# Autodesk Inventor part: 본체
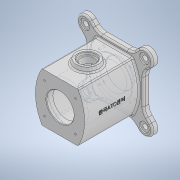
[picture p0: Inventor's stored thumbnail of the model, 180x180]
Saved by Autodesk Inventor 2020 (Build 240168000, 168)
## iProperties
Created: 2022-01
Part Number: 본체
Material: 일반
Document SubType Name: Modeling
Designer: user
Density: 1 g/cm^3
Appearance: 기본값
Mass: 458.422 g
Surface Area: 905.599 cm^2
Volume: 458.422 cm^3
Author: user
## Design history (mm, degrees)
sketch "스케치1"
  geometry: L1 (-32.942, -45)-(32.942, -45); L2 (32.942, 45)-(-32.942, 45); L3 (-45, -45)-(45, 45); L4 (45, -45)-(-45, 45); L5 (0, 0)-(0, -45); A1 r 90 centre (45, 0) between (-32.942, 45) and (-32.942, -45); A2 r 90 centre (-45, 0) between (32.942, -45) and (32.942, 45)
  constraints: 10 end point, 4 point on circle, 3 symmetric about line, 2 centre point, 2 midpoint, 1 horizontal, 1 parallel, 1 other
  dimensions: "d2" = 180 diameter of A1; "d3" = 90 distance between parallel lines of L1 L2; "d4" = 90 distance of A1.centre A2.centre
extrude "돌출1" new body sketch "스케치1" distance "d5" = 110; taper "d6" = 0 deg
sketch "스케치2"
  geometry: L1 (53, -53)-(-53, -53); L2 (-53, -53)-(-53, 53); L3 (-53, 53)-(53, 53); L4 (53, 53)-(53, -53); L5 (53, -53)-(-53, 53); L6 (-53, -53)-(53, 53); L7 (0, 0)-(0, 74); L8 (54.447, -54.447)-(-54.447, 54.447); L9 (65.054, -43.841)-(-43.841, 65.054); L10 (-65.054, 43.841)-(43.841, -65.054); L11 (-54.447, -54.447)-(54.447, 54.447); L12 (-43.841, -65.054)-(65.054, 43.841); L13 (43.841, 65.054)-(-65.054, -43.841); A1 r 15 centre (54.447, -54.447) between (43.841, -65.054) and (65.054, -43.841); A2 r 15 centre (-54.447, 54.447) between (-43.841, 65.054) and (-65.054, 43.841); A3 r 15 centre (-54.447, -54.447) between (-65.054, -43.841) and (-43.841, -65.054); A4 r 15 centre (54.447, 54.447) between (65.054, 43.841) and (43.841, 65.054); 9 further points
  constraints: 30 end point, 8 point on circle, 8 tangent, 5 midpoint, 4 centre point, 4 parallel, 2 perpendicular, 2 point on line, 1 horizontal, 1 vertical
  dimensions: "d7" = 106 distance of L2.end L3.end; "d8" = 106 distance of L1.end L2.end; "d10" = 154 distance of L11.start L11.end; "d11" = 154 distance of L8.start L8.end; "d12" = 30 distance between parallel lines of L12 L13; "d13" = 30 distance between parallel lines of L10 L9
extrude "돌출2" join sketch "스케치2" distance "d14" = 10; taper "d15" = 0 deg
fillet "모깎기1" dims "d16" = 20
sketch "스케치3"
  geometry: L1 (25, 110)-(25, 98); L2 (25, 98)-(-25, 98); L3 (-25, 98)-(-25, 110); L4 (32.942, 110)-(-32.942, 110) reference; L5 (-25, 122)-(25, 98); L6 (25, 122)-(-25, 98); L7 (-25, 12)-(25, 12); L8 (25, 12)-(25, 0); L9 (-25, 0)-(-25, 12); L10 (-25, 12)-(25, -12); L11 (25, 12)-(-25, -12); L12 (-23.503, 0)-(23.503, 0) reference; L13 (23.503, 0)-(37.645, 0) reference; L14 (-37.645, 0)-(-23.503, 0) reference; L15 (25, 110)-(-25, 110); L16 (0, 55)-(-37, 55); L17 (-45, 10)-(-45, 110) reference; L18 (-37, 55)-(-37, 98); L19 (-37, 98)-(-25, 98); L20 (-37, 12)-(-25, 12); L21 (-37, 55)-(-37, 12); L22 (0, 110)-(0, 0); 2 further points
  constraints: 34 end point, 5 midpoint, 4 point on line, 3 perpendicular, 2 parallel, 2 symmetric about line, 2 vertical, 1 horizontal
  dimensions: "d17" = 50 distance of L1.end L2.end; "d21" = 37 distance of L16.start L16.end; "d22" = 86 distance between parallel lines of L20 L19; "d23" = 12 distance between parallel lines of L4 L2; "d24" = 12 distance between parallel lines of L12 L7
revolve "회전1" sketch "스케치3" stored, may be unused: angle "d25" = 90 deg
node "작업 평면1"
sketch "스케치4"
  geometry: L1 (0, 0)-(0, 60); C1 r 20 at (0, 60)
  constraints: 2 end point, 1 centre point, 1 coincident, 1 vertical
  dimensions: "d27" = 60 distance of L1.start L1.end; "d28" = 40 diameter of C1
extrude "돌출3" join sketch "스케치4" stored distance "d29" = 5; taper "d30" = 15 deg
sketch "스케치5"
  geometry: C1 r 15 at (0, 0); 1 further point
  constraints: 1 centre point
  dimensions: "d31" = 30 diameter of C1
extrude "돌출4" cut sketch "스케치5" distance "d32" = 5; taper "d33" = 0 deg
sketch "스케치6"
  geometry: C1 r 12 at (0, 0); 1 further point
  constraints: 1 centre point
  dimensions: "d34" = 24 diameter of C1
extrude "돌출5" cut sketch "스케치6" distance "d35" = 48; taper "d36" = 0 deg
sketch "스케치7"
  geometry: C1 r 9 at (54.447, 54.447); A1 r 15 centre (54.447, 54.447) between (65.054, 43.841) and (43.841, 65.054) reference; 1 further point
  constraints: 1 centre point, 1 coincident
  dimensions: "d37" = 18 diameter of C1
extrude "돌출6" cut sketch "스케치7" distance "d38" = 2; taper "d39" = 0 deg
sketch "스케치8"
  geometry: C1 r 4.5 at (0, 0); 1 further point
  constraints: 1 centre point
  dimensions: "d40" = 9 diameter of C1
extrude "돌출7" cut sketch "스케치8" stored distance "d41" = 2; taper "d42" = 0 deg
fillet "모깎기2" dims "d46" = 3
fillet "모깎기3" dims "d47" = 3
fillet "모깎기4" dims "d48" = 3
fillet "모깎기5" dims "d49" = 3
fillet "모깎기6" dims "d50" = 3
chamfer "모따기1" distance "d51" = 1; stored, may be unused: second distance "d52" = 2, angle "d53" = 45 deg
sketch "스케치9"
  geometry: L1 (-28.284, 28.284)-(28.284, -28.284); L2 (-48.784, 7.784)-(7.784, -48.784); L3 (48.784, -7.784)-(-7.784, 48.784); L4 (0, 0)-(80, 0); L5 (-28.284, -28.284)-(28.284, 28.284); L6 (-41.284, -15.284)-(15.284, 41.284); L7 (41.284, 15.284)-(-15.284, -41.284); L8 (0, 0)-(80, 0); C1 r 25 at (0, 0) reference; A1 r 28.991 centre (-28.284, 28.284) between (-7.784, 48.784) and (-48.784, 7.784); A2 r 28.991 centre (28.284, -28.284) between (7.784, -48.784) and (48.784, -7.784); A3 r 18.385 centre (-28.284, -28.284) between (-41.284, -15.284) and (-15.284, -41.284); A4 r 18.385 centre (28.284, 28.284) between (41.284, 15.284) and (15.284, 41.284)
  constraints: 20 end point, 8 point on circle, 8 tangent, 4 centre point, 2 equal length, 2 horizontal, 2 midpoint, 2 parallel
  dimensions: "d77" = 45 deg angle of L1 L4; "d78" = 45 deg angle of L8 L5; "d79" = 80 distance of L5.start L5.end; "d80" = 80 distance of L1.start L1.end
hole "구멍1" sketch "스케치9" at (28.284, -28.284), (28.284, 28.284), (-28.284, 28.284), (-28.284, -28.284) diameter "d57" = 3.242; stored, may be unused: countersink angle "d61" = 90 deg, drill point angle "d63" = 118 deg; dims "d58" = 8, "d59" = 4, "d60" = 2, "d62" = 10
node "작업 평면2"
node "작업 평면3"
sketch "스케치10" dims "d2" = 180, "d3" = 90, "d4" = 90
  geometry: L1 (53, 40)-(53, 80) reference; L2 (43.841, 0)-(69.447, 0) reference; 3 further points
  constraints: 1 other
  dimensions: "d69" = 53 distance from line of L1 point (0, 60); "d70" = 60 distance from line of L2 point (0, 60)
feature "엠보싱1" sketch "스케치10" dims "d2" = 180, "d71" = 0.5, "d72" = 0
node "솔리드1"
pattern_circular "원형 패턴1" dims angle "d44" = 360 deg
mirror "미러3"
feature "A9D066F2-1C7D-4E18-AEED-F7BC21143FA4" dims "d57" = 3.242, "d58" = 8, "d59" = 4, "d60" = 2, "d61" = 90 deg, "d62" = 10, "d63" = 118 deg
other parameters: "d26" = 53, "d67" = -55, "d68" = 45
